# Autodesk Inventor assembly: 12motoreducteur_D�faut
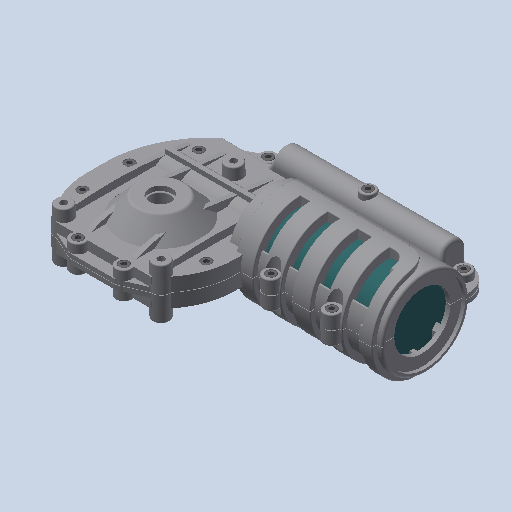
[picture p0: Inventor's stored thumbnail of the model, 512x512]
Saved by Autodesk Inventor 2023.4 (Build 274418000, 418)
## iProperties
Created: 2011-01
Part Number: 12motoreducteur_D�faut
Document SubType Name: Assembly
Designer: eric
Mass: 915.076 g
Surface Area: 3343.24 cm^2
Volume: 915.076 cm^3
Density: 1 g/cm^3
Author: eric
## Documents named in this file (12)
- C:\Users\bruno\Documents\1-Cours-2024-25\TSsI\7-Dynamique\chariot de golf\chariot_de_golf\chariot_de_golf_trolem\12motoreducteur_Defaut.iam
- C:\Users\bruno\Documents\1-Cours-2024-25\TSsI\7-Dynamique\chariot de golf\chariot_de_golf\chariot_de_golf_trolem\12Ecrou_freineM5.ipt
- C:\Users\bruno\Documents\1-Cours-2024-25\TSsI\7-Dynamique\chariot de golf\chariot_de_golf\chariot_de_golf_trolem\12VisCHC M5-20_Defaut.ipt
- C:\Users\bruno\Documents\1-Cours-2024-25\TSsI\7-Dynamique\chariot de golf\chariot_de_golf\chariot_de_golf_trolem\12Roulement_BC17x40x12_Defaut.iam
- C:\Users\bruno\Documents\1-Cours-2024-25\TSsI\7-Dynamique\chariot de golf\chariot_de_golf\chariot_de_golf_trolem\tube_Defaut.ipt
- C:\Users\bruno\Documents\1-Cours-2024-25\TSsI\7-Dynamique\chariot de golf\chariot_de_golf\chariot_de_golf_trolem\12VisCHC M5-55_Defaut.ipt
- C:\Users\bruno\Documents\1-Cours-2024-25\TSsI\7-Dynamique\chariot de golf\chariot_de_golf\chariot_de_golf_trolem\12Roulement_BC8x22x7_Defaut.iam
- C:\Users\bruno\Documents\1-Cours-2024-25\TSsI\7-Dynamique\chariot de golf\chariot_de_golf\chariot_de_golf_trolem\12VisCHC M5-16_Defaut.ipt
- C:\Users\bruno\Documents\1-Cours-2024-25\TSsI\7-Dynamique\chariot de golf\chariot_de_golf\chariot_de_golf_trolem\12coquille_gauche_Defaut.ipt
- C:\Users\bruno\Documents\1-Cours-2024-25\TSsI\7-Dynamique\chariot de golf\chariot_de_golf\chariot_de_golf_trolem\12coquille_droite_Defaut.ipt
- C:\Users\bruno\Documents\1-Cours-2024-25\TSsI\7-Dynamique\chariot de golf\chariot_de_golf\chariot_de_golf_trolem\12moteur_Defaut.ipt
- C:\Users\bruno\Documents\1-Cours-2024-25\TSsI\7-Dynamique\chariot de golf\chariot_de_golf\chariot_de_golf_trolem\12joint_etancheite_Defaut.ipt
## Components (35 placed, 11 different names)
1. 12Ecrou_freineM5:1
2. 12Ecrou_freineM5:2
3. 12VisCHC M5-20_Defaut:1
4. 12Roulement_BC17x40x12_Defaut:1 [sub-assembly]
5. 12Ecrou_freineM5:3
6. 12VisCHC M5-20_Defaut:2
7. 12VisCHC M5-20_Defaut:3
8. tube_Defaut:1
9. 12Ecrou_freineM5:4
10. 12VisCHC M5-20_Defaut:4
11. 12VisCHC M5-20_Defaut:5
12. 12Ecrou_freineM5:5
13. 12VisCHC M5-20_Defaut:6
14. 12Ecrou_freineM5:6
15. 12Ecrou_freineM5:7
16. 12VisCHC M5-55_Defaut:1
17. 12Roulement_BC17x40x12_Defaut:2 [sub-assembly]
18. 12Roulement_BC8x22x7_Defaut:1 [sub-assembly]
19. 12VisCHC M5-16_Defaut:1
20. 12Ecrou_freineM5:8
21. 12VisCHC M5-20_Defaut:7
22. 12coquille_gauche_Defaut:1
23. 12coquille_droite_Defaut:1
24. 12Ecrou_freineM5:9
25. 12Ecrou_freineM5:10
26. 12VisCHC M5-20_Defaut:8
27. 12moteur_Defaut:1
28. 12Ecrou_freineM5:11
29. 12Ecrou_freineM5:12
30. 12VisCHC M5-20_Defaut:9
31. 12VisCHC M5-16_Defaut:2
32. 12joint_etancheite_Defaut:1
33. 12Roulement_BC8x22x7_Defaut:2 [sub-assembly]
34. 12VisCHC M5-20_Defaut:10
35. 12Ecrou_freineM5:13
